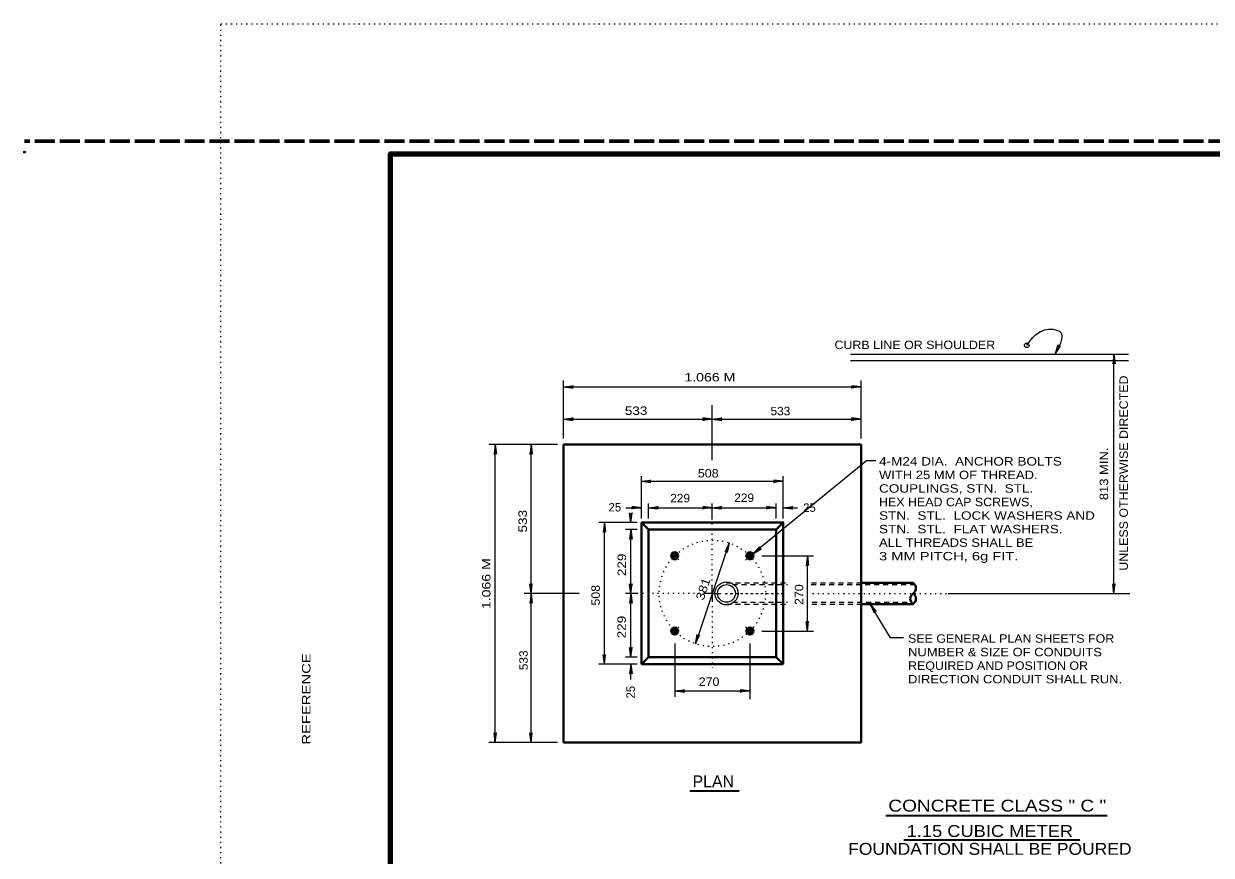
# Model space of a CAD drawing. Extents: x 312583 to 312854, y 144419 to 144597.
# Drawn here: x 312583.5 to 312690.4, y 144521.9 to 144596.8 of the extents above; entities that cross this region are included whole.
import ezdxf
from ezdxf.enums import TextEntityAlignment as Align

# ---------------------------------------------------------------- set-up
doc = ezdxf.new("R2010")
doc.units = 0
doc.header["$LTSCALE"] = 0.3
doc.header["$PDMODE"] = 32
doc.header["$PDSIZE"] = 0.15
for name, pattern in [('DOTTED', [1.5, 0.3, -1.2]), ('LONG_DASHED', [7.5, 6, -1.5]), ('SHORT_DASHED', [2.7, 1.5, -1.2])]:
    doc.linetypes.add(name, pattern=pattern)
for name, color, linetype, lineweight in [('1', 7, 'Continuous', 25), ('2', 7, 'Continuous', 13), ('62', 7, 'DOTTED', 13), ('63', 7, 'LONG_DASHED', 60)]:
    doc.layers.add(name, color=color, linetype=linetype, lineweight=lineweight)

msp = doc.modelspace()

# ---------------------------------------------------------------- linework, layer by layer
at = {"layer": '1', "lineweight": 40}
for p, q in [((312632.0713, 144558.8961), (312658.9047, 144558.8961)), ((312632.0713, 144558.8961), (312632.0713, 144532.0628)), ((312658.9047, 144558.8961), (312658.9047, 144532.0628)), ((312639.094, 144551.8734), (312639.094, 144539.0931)), ((312639.738, 144551.2294), (312639.094, 144551.8734)), ((312651.238, 144551.2294), (312651.8743, 144551.8734)), ((312639.738, 144551.2294), (312639.738, 144539.7294)), ((312639.738, 144551.2294), (312651.238, 144551.2294)), ((312651.238, 144551.2294), (312651.238, 144539.7294)), ((312658.9047, 144546.4378), (312663.5737, 144546.4378)), ((312658.9047, 144544.5211), (312663.5737, 144544.5211)), ((312639.094, 144539.0931), (312639.738, 144539.7294)), ((312639.094, 144539.0931), (312651.8743, 144539.0931)), ((312639.738, 144539.7294), (312651.238, 144539.7294)), ((312651.238, 144539.7294), (312651.8743, 144539.0931)), ((312632.0713, 144532.0628), (312658.9047, 144532.0628))]:
    msp.add_line(p, q, dxfattribs=at)
at = {"layer": '1', "linetype": 'DOTTED', "lineweight": 13}
for p, q in [((312642.475, 144548.4924), (312641.8157, 144549.1518)), ((312648.4857, 144548.4848), (312648.8767, 144548.8681)), ((312646.7607, 144545.4794), (312652.2577, 144545.4794)), ((312654.527, 144545.4794), (312666.7477, 144545.4794)), ((312642.4673, 144542.4664), (312641.8157, 144541.8148)), ((312648.4857, 144542.4818), (312649.1527, 144541.8148))]:
    msp.add_line(p, q, dxfattribs=at)
at = {"layer": '1', "linetype": 'SHORT_DASHED'}
for p, q in [((312646.7607, 144546.4378), (312652.2577, 144546.4378)), ((312647.2973, 144546.2844), (312652.2577, 144546.2844)), ((312654.3967, 144546.2844), (312663.727, 144546.2844)), ((312654.4197, 144546.4378), (312658.9047, 144546.4378)), ((312646.7607, 144544.5211), (312652.2577, 144544.5211)), ((312647.2973, 144544.6821), (312652.2577, 144544.6821)), ((312654.458, 144544.5211), (312658.9047, 144544.5211)), ((312654.481, 144544.6821), (312663.4203, 144544.6821))]:
    msp.add_line(p, q, dxfattribs=at)
at = {"layer": '1', "lineweight": 158}
msp.add_lwpolyline([(312616.5, 144423.1446), (312616.5, 144585.0846), (312849, 144585.0846)], dxfattribs=at)
at = {"layer": '1', "lineweight": 40}
msp.add_lwpolyline([(312639.094, 144551.8734), (312651.8743, 144551.8734), (312651.8743, 144539.0931)], dxfattribs=at)
at = {"layer": '1', "linetype": 'DOTTED', "lineweight": 13}
msp.add_circle((312645.4861, 144545.4826), 4.7917, dxfattribs=at)
at = {"layer": '1', "lineweight": 40}
for centre, radius in [((312642.0981, 144548.8707), 0.3194), ((312642.0981, 144548.8707), 0.2236), ((312642.0978, 144548.8709), 0.1565), ((312642.0979, 144548.8708), 0.1096), ((312648.8741, 144548.8707), 0.3194), ((312648.8741, 144548.8707), 0.2236), ((312648.8741, 144548.8707), 0.1565), ((312648.8741, 144548.8707), 0.1096), ((312642.0981, 144542.0946), 0.3194), ((312642.0981, 144542.0946), 0.2236), ((312642.0981, 144542.0946), 0.1565), ((312642.0981, 144542.0946), 0.1096), ((312648.8741, 144542.0946), 0.3194), ((312648.8741, 144542.0946), 0.2236), ((312648.8741, 144542.0946), 0.1565), ((312648.8741, 144542.0946), 0.1096)]:
    msp.add_circle(centre, radius, dxfattribs=at)
at = {"layer": '1'}
for radius in [1.0382, 0.7986]:
    msp.add_circle((312646.7639, 144545.4826), radius, dxfattribs=at)
at = {"layer": '1', "lineweight": 40}
for centre, start, end in [((312663.242, 144545.9618), 304.79073, 55.20927), ((312663.9079, 144545.0035), 124.79073, 235.20928), ((312663.242, 144545.0035), 304.79073, 55.20927)]:
    msp.add_arc(centre, 0.5835, start, end, dxfattribs=at)
at = {"layer": '1'}
msp.add_point((312583.526, 144585.2246), dxfattribs=at)
at = {"layer": '2'}
for p, q in [((312676.3884, 144567.0304), (312676.6567, 144567.8584)), ((312676.3884, 144567.0304), (312676.8484, 144567.7664)), ((312676.6567, 144567.8584), (312676.6414, 144567.5671)), ((312676.8484, 144567.7664), (312676.6414, 144567.5671)), ((312657.9233, 144567.0304), (312682.98, 144567.0304)), ((312681.6734, 144567.0304), (312681.5661, 144566.1641)), ((312681.6734, 144545.4794), (312681.6734, 144567.0304)), ((312681.6734, 144567.0304), (312681.7808, 144566.1641)), ((312657.9233, 144566.4478), (312682.98, 144566.4478)), ((312681.5661, 144566.1641), (312681.6734, 144566.4401)), ((312681.7808, 144566.1641), (312681.6734, 144566.4401)), ((312632.0713, 144559.4328), (312632.0713, 144564.6614)), ((312632.0713, 144559.4328), (312632.0713, 144564.6614)), ((312658.9047, 144559.4328), (312658.9047, 144564.6614)), ((312658.9047, 144559.4328), (312658.9047, 144564.5924)), ((312632.0713, 144564.0788), (312632.9377, 144564.1861)), ((312632.0713, 144564.0788), (312632.9377, 144564.1861)), ((312632.0713, 144564.0788), (312658.9047, 144564.0788)), ((312632.0713, 144564.0788), (312632.9377, 144563.9714)), ((312632.0713, 144564.0788), (312658.9047, 144564.0788)), ((312632.0713, 144564.0788), (312632.9377, 144563.9714)), ((312632.9377, 144564.1861), (312632.6617, 144564.0788)), ((312632.9377, 144564.1861), (312632.6617, 144564.0788)), ((312632.9377, 144563.9714), (312632.6617, 144564.0788)), ((312632.9377, 144563.9714), (312632.6617, 144564.0788)), ((312658.0383, 144564.1861), (312658.3143, 144564.0788)), ((312658.9047, 144564.0788), (312658.0383, 144564.1861)), ((312658.0383, 144564.1861), (312658.3143, 144564.0788)), ((312658.9047, 144564.0788), (312658.0383, 144564.1861)), ((312658.0383, 144563.9714), (312658.3143, 144564.0788)), ((312658.9047, 144564.0788), (312658.0383, 144563.9714)), ((312658.0383, 144563.9714), (312658.3143, 144564.0788)), ((312658.9047, 144564.0788), (312658.0383, 144563.9714)), ((312645.488, 144557.4778), (312645.488, 144562.4458)), ((312632.0713, 144561.1731), (312632.9377, 144561.2804)), ((312632.0713, 144561.1731), (312632.9377, 144561.2804)), ((312632.9377, 144561.2804), (312632.6617, 144561.1731)), ((312632.9377, 144561.2804), (312632.6617, 144561.1731)), ((312644.6217, 144561.2804), (312644.8977, 144561.1731)), ((312645.488, 144561.1731), (312644.6217, 144561.2804)), ((312644.6217, 144561.2804), (312644.8977, 144561.1731)), ((312645.488, 144561.1731), (312644.6217, 144561.2804)), ((312645.488, 144557.4778), (312645.488, 144561.6944)), ((312645.488, 144561.1731), (312646.3543, 144561.2804)), ((312645.488, 144561.1731), (312646.3543, 144561.2804)), ((312646.3543, 144561.2804), (312646.0783, 144561.1731)), ((312646.3543, 144561.2804), (312646.0783, 144561.1731)), ((312658.0383, 144561.2804), (312658.3143, 144561.1731)), ((312658.9047, 144561.1731), (312658.0383, 144561.2804)), ((312658.0383, 144561.2804), (312658.3143, 144561.1731)), ((312658.9047, 144561.1731), (312658.0383, 144561.2804)), ((312632.0713, 144561.1731), (312632.9377, 144561.0658)), ((312632.0713, 144561.1731), (312632.9377, 144561.0658)), ((312632.9377, 144561.0658), (312632.6617, 144561.1731)), ((312632.9377, 144561.0658), (312632.6617, 144561.1731)), ((312644.6217, 144561.0658), (312644.8977, 144561.1731)), ((312645.488, 144561.1731), (312644.6217, 144561.0658)), ((312644.6217, 144561.0658), (312644.8977, 144561.1731)), ((312645.488, 144561.1731), (312644.6217, 144561.0658)), ((312645.488, 144561.1731), (312646.3543, 144561.0658)), ((312645.488, 144561.1731), (312646.3543, 144561.0658)), ((312646.3543, 144561.0658), (312646.0783, 144561.1731)), ((312646.3543, 144561.0658), (312646.0783, 144561.1731)), ((312658.0383, 144561.0658), (312658.3143, 144561.1731)), ((312658.9047, 144561.1731), (312658.0383, 144561.0658)), ((312658.0383, 144561.0658), (312658.3143, 144561.1731)), ((312658.9047, 144561.1731), (312658.0383, 144561.0658)), ((312631.5347, 144558.8961), (312625.3477, 144558.8961)), ((312631.5347, 144558.8961), (312625.3477, 144558.8961)), ((312625.9303, 144558.8961), (312625.823, 144558.0298)), ((312625.9303, 144558.8961), (312625.823, 144558.0298)), ((312625.823, 144558.0298), (312625.9303, 144558.3058)), ((312625.823, 144558.0298), (312625.9303, 144558.3058)), ((312625.9303, 144532.0628), (312625.9303, 144558.8961)), ((312625.9303, 144558.8961), (312626.0377, 144558.0298)), ((312625.9303, 144532.0628), (312625.9303, 144558.8961)), ((312625.9303, 144558.8961), (312626.0377, 144558.0298)), ((312626.0377, 144558.0298), (312625.9303, 144558.3058)), ((312626.0377, 144558.0298), (312625.9303, 144558.3058)), ((312629.158, 144558.8961), (312629.0507, 144558.0298)), ((312629.158, 144558.8961), (312629.0507, 144558.0298)), ((312629.0507, 144558.0298), (312629.158, 144558.3058)), ((312629.0507, 144558.0298), (312629.158, 144558.3058)), ((312629.158, 144558.8961), (312629.2653, 144558.0298)), ((312629.158, 144558.8961), (312629.2653, 144558.0298)), ((312629.2653, 144558.0298), (312629.158, 144558.3058)), ((312629.2653, 144558.0298), (312629.158, 144558.3058)), ((312659.3647, 144557.4088), (312649.145, 144549.0368)), ((312660.2157, 144557.4088), (312659.3647, 144557.4088)), ((312639.094, 144552.2414), (312639.094, 144556.0518)), ((312651.8743, 144552.2414), (312651.8743, 144556.0518)), ((312639.094, 144555.5764), (312639.9603, 144555.6838)), ((312639.094, 144555.5764), (312651.8743, 144555.5764)), ((312639.094, 144555.5764), (312639.9603, 144555.4691)), ((312639.9603, 144555.6838), (312639.6843, 144555.5764)), ((312639.9603, 144555.4691), (312639.6843, 144555.5764)), ((312651.008, 144555.6838), (312651.284, 144555.5764)), ((312651.8743, 144555.5764), (312651.008, 144555.6838)), ((312651.008, 144555.4691), (312651.284, 144555.5764)), ((312651.8743, 144555.5764), (312651.008, 144555.4691)), ((312637.691, 144553.1921), (312639.094, 144553.1921)), ((312638.036, 144552.7398), (312638.1433, 144552.4638)), ((312638.1433, 144551.8734), (312638.036, 144552.7398)), ((312638.2507, 144552.7398), (312638.1433, 144552.4638)), ((312638.1433, 144551.8734), (312638.2507, 144552.7398)), ((312638.2277, 144553.2994), (312638.5037, 144553.1921)), ((312639.094, 144553.1921), (312638.2277, 144553.2994)), ((312638.2277, 144553.0848), (312638.5037, 144553.1921)), ((312639.094, 144553.1921), (312638.2277, 144553.0848)), ((312639.738, 144552.2414), (312639.738, 144553.5678)), ((312639.738, 144553.1921), (312640.6043, 144553.2994)), ((312639.738, 144553.1921), (312645.488, 144553.1921)), ((312639.738, 144553.1921), (312640.6043, 144553.0848)), ((312640.6043, 144553.2994), (312640.3283, 144553.1921)), ((312640.6043, 144553.0848), (312640.3283, 144553.1921)), ((312644.6217, 144553.2994), (312644.8977, 144553.1921)), ((312645.488, 144553.1921), (312644.6217, 144553.2994)), ((312644.6217, 144553.0848), (312644.8977, 144553.1921)), ((312645.488, 144553.1921), (312644.6217, 144553.0848)), ((312645.488, 144552.2108), (312645.488, 144553.5678)), ((312645.488, 144553.1921), (312646.3543, 144553.2994)), ((312645.488, 144553.1921), (312651.238, 144553.1921)), ((312645.488, 144553.1921), (312646.3543, 144553.0848)), ((312646.3543, 144553.2994), (312646.0783, 144553.1921)), ((312646.3543, 144553.0848), (312646.0783, 144553.1921)), ((312650.3717, 144553.2994), (312650.6477, 144553.1921)), ((312651.238, 144553.1921), (312650.3717, 144553.2994)), ((312650.3717, 144553.0848), (312650.6477, 144553.1921)), ((312651.238, 144553.1921), (312650.3717, 144553.0848)), ((312651.238, 144552.2414), (312651.238, 144553.5678)), ((312651.8743, 144553.1921), (312652.7407, 144553.2994)), ((312651.8743, 144553.1921), (312653.17, 144553.1921)), ((312651.8743, 144553.1921), (312652.7407, 144553.0848)), ((312652.7407, 144553.2994), (312652.4647, 144553.1921)), ((312652.7407, 144553.0848), (312652.4647, 144553.1921)), ((312638.726, 144551.8734), (312635.2607, 144551.8734)), ((312635.7667, 144551.8734), (312635.6593, 144551.0071)), ((312635.7667, 144539.0931), (312635.7667, 144551.8734)), ((312635.7667, 144551.8734), (312635.874, 144551.0071)), ((312638.1433, 144551.8734), (312638.1433, 144552.6631)), ((312635.6593, 144551.0071), (312635.7667, 144551.2831)), ((312635.874, 144551.0071), (312635.7667, 144551.2831)), ((312638.726, 144551.2294), (312637.668, 144551.2294)), ((312638.1433, 144551.2294), (312638.036, 144550.3631)), ((312638.036, 144550.3631), (312638.1433, 144550.6391)), ((312638.1433, 144551.2294), (312638.2507, 144550.3631)), ((312638.2507, 144550.3631), (312638.1433, 144550.6391)), ((312647.0137, 144550.0258), (312643.9623, 144540.9408)), ((312647.0137, 144550.0258), (312646.638, 144549.2361)), ((312647.0137, 144550.0258), (312646.8373, 144549.1671)), ((312649.145, 144549.0368), (312649.7507, 144549.6654)), ((312649.145, 144549.0368), (312649.8887, 144549.5044)), ((312649.7507, 144549.6654), (312649.605, 144549.4124)), ((312649.8887, 144549.5044), (312649.605, 144549.4124)), ((312646.638, 144549.2361), (312646.822, 144549.4661)), ((312646.8373, 144549.1671), (312646.822, 144549.4661)), ((312649.9347, 144548.8681), (312654.5883, 144548.8681)), ((312654.0593, 144548.8681), (312653.952, 144548.0018)), ((312654.0593, 144542.0908), (312654.0593, 144548.8681)), ((312654.0593, 144548.8681), (312654.1667, 144548.0018)), ((312653.952, 144548.0018), (312654.0593, 144548.2778)), ((312654.1667, 144548.0018), (312654.0593, 144548.2778)), ((312629.0507, 144546.3458), (312629.158, 144546.0698)), ((312629.158, 144545.4794), (312629.0507, 144546.3458)), ((312629.0507, 144546.3458), (312629.158, 144546.0698)), ((312629.158, 144545.4794), (312629.0507, 144546.3458)), ((312629.2653, 144546.3458), (312629.158, 144546.0698)), ((312629.158, 144545.4794), (312629.2653, 144546.3458)), ((312629.2653, 144546.3458), (312629.158, 144546.0698)), ((312629.158, 144545.4794), (312629.2653, 144546.3458)), ((312638.036, 144546.3458), (312638.1433, 144546.0698)), ((312638.1433, 144545.4794), (312638.036, 144546.3458)), ((312638.2507, 144546.3458), (312638.1433, 144546.0698)), ((312638.1433, 144545.4794), (312638.2507, 144546.3458)), ((312681.5661, 144546.3458), (312681.6734, 144546.0698)), ((312681.6734, 144545.4794), (312681.5661, 144546.3458)), ((312681.7808, 144546.3458), (312681.6734, 144546.0698)), ((312681.6734, 144545.4794), (312681.7808, 144546.3458)), ((312633.4897, 144545.4794), (312628.5217, 144545.4794)), ((312633.4897, 144545.4794), (312628.5217, 144545.4794)), ((312629.158, 144545.4794), (312629.0507, 144544.6131)), ((312629.158, 144545.4794), (312629.0507, 144544.6131)), ((312629.158, 144545.4794), (312629.2653, 144544.6131)), ((312629.158, 144532.0628), (312629.158, 144545.4794)), ((312629.158, 144545.4794), (312629.2653, 144544.6131)), ((312638.7797, 144545.4794), (312637.668, 144545.4794)), ((312638.1433, 144545.4794), (312638.036, 144544.6131)), ((312638.1433, 144545.4794), (312638.2507, 144544.6131)), ((312645.488, 144545.4794), (312644.7213, 144545.4794)), ((312645.488, 144545.4794), (312645.488, 144546.2461)), ((312645.488, 144545.4794), (312646.2547, 144545.4794)), ((312645.488, 144545.4794), (312645.488, 144544.7128)), ((312666.7477, 144545.4794), (312683.0921, 144545.4794)), ((312629.0507, 144544.6131), (312629.158, 144544.8891)), ((312629.0507, 144544.6131), (312629.158, 144544.8891)), ((312629.2653, 144544.6131), (312629.158, 144544.8891)), ((312629.2653, 144544.6131), (312629.158, 144544.8891)), ((312638.036, 144544.6131), (312638.1433, 144544.8891)), ((312638.2507, 144544.6131), (312638.1433, 144544.8891)), ((312659.7097, 144544.5211), (312660.0623, 144543.7238)), ((312659.7097, 144544.5211), (312660.2463, 144543.8388)), ((312660.0623, 144543.7238), (312660.0087, 144544.0151)), ((312660.2463, 144543.8388), (312660.0087, 144544.0151)), ((312649.9347, 144542.0908), (312654.5883, 144542.0908)), ((312653.952, 144542.9571), (312654.0593, 144542.6811)), ((312654.0593, 144542.0908), (312653.952, 144542.9571)), ((312654.1667, 144542.9571), (312654.0593, 144542.6811)), ((312654.0593, 144542.0908), (312654.1667, 144542.9571)), ((312642.0993, 144540.9791), (312642.0993, 144536.1721)), ((312643.9623, 144540.9408), (312644.131, 144541.7918)), ((312643.9623, 144540.9408), (312644.338, 144541.7304)), ((312644.131, 144541.7918), (312644.1463, 144541.5004)), ((312644.338, 144541.7304), (312644.1463, 144541.5004)), ((312648.8767, 144540.9791), (312648.8767, 144535.9421)), ((312635.6593, 144539.9594), (312635.7667, 144539.6834)), ((312635.7667, 144539.0931), (312635.6593, 144539.9594)), ((312635.874, 144539.9594), (312635.7667, 144539.6834)), ((312635.7667, 144539.0931), (312635.874, 144539.9594)), ((312638.036, 144540.5958), (312638.1433, 144540.3198)), ((312638.1433, 144539.7294), (312638.036, 144540.5958)), ((312638.2507, 144540.5958), (312638.1433, 144540.3198)), ((312638.1433, 144539.7294), (312638.2507, 144540.5958)), ((312638.726, 144539.0931), (312635.2607, 144539.0931)), ((312638.726, 144539.7294), (312637.668, 144539.7294)), ((312638.1433, 144539.0931), (312638.036, 144538.2268)), ((312638.1433, 144537.7208), (312638.1433, 144539.0931)), ((312638.1433, 144539.0931), (312638.2507, 144538.2268)), ((312638.036, 144538.2268), (312638.1433, 144538.5028)), ((312638.2507, 144538.2268), (312638.1433, 144538.5028)), ((312642.0993, 144536.6934), (312642.9657, 144536.8008)), ((312642.0993, 144536.6934), (312648.8767, 144536.6934)), ((312642.0993, 144536.6934), (312642.9657, 144536.5861)), ((312642.9657, 144536.8008), (312642.6897, 144536.6934)), ((312642.9657, 144536.5861), (312642.6897, 144536.6934)), ((312648.0103, 144536.8008), (312648.2863, 144536.6934)), ((312648.8767, 144536.6934), (312648.0103, 144536.8008)), ((312648.0103, 144536.5861), (312648.2863, 144536.6934)), ((312648.8767, 144536.6934), (312648.0103, 144536.5861)), ((312625.823, 144532.9291), (312625.9303, 144532.6531)), ((312625.9303, 144532.0628), (312625.823, 144532.9291)), ((312625.823, 144532.9291), (312625.9303, 144532.6531)), ((312625.9303, 144532.0628), (312625.823, 144532.9291)), ((312626.0377, 144532.9291), (312625.9303, 144532.6531)), ((312625.9303, 144532.0628), (312626.0377, 144532.9291)), ((312626.0377, 144532.9291), (312625.9303, 144532.6531)), ((312625.9303, 144532.0628), (312626.0377, 144532.9291)), ((312629.0507, 144532.9291), (312629.158, 144532.6531)), ((312629.158, 144532.0628), (312629.0507, 144532.9291)), ((312629.0507, 144532.9291), (312629.158, 144532.6531)), ((312629.158, 144532.0628), (312629.0507, 144532.9291)), ((312629.2653, 144532.9291), (312629.158, 144532.6531)), ((312629.158, 144532.0628), (312629.2653, 144532.9291)), ((312629.2653, 144532.9291), (312629.158, 144532.6531)), ((312629.158, 144532.0628), (312629.2653, 144532.9291)), ((312631.5347, 144532.0628), (312625.3477, 144532.0628)), ((312631.5347, 144532.0628), (312625.3477, 144532.0628))]:
    msp.add_line(p, q, dxfattribs=at)
at = {"layer": '2', "linetype": 'DOTTED'}
for p, q in [((312645.488, 144546.6294), (312645.488, 144552.2108)), ((312644.338, 144545.4794), (312638.7797, 144545.4794)), ((312646.638, 144545.4794), (312652.135, 144545.4794)), ((312645.488, 144544.3294), (312645.488, 144538.7788))]:
    msp.add_line(p, q, dxfattribs=at)
at = {"layer": '2', "lineweight": 35}
for p, q in [((312643.459, 144527.7068), (312647.9131, 144527.7068)), ((312661.1113, 144525.4666), (312681.0557, 144525.4666)), ((312662.7517, 144523.2829), (312678.5924, 144523.2829))]:
    msp.add_line(p, q, dxfattribs=at)
at = {"layer": '2'}
for points in [[(312632.0713, 144561.1731), (312645.488, 144561.1731), (312658.9047, 144561.1731)], [(312632.0713, 144561.1731), (312645.488, 144561.1731), (312658.9047, 144561.1731)], [(312629.158, 144532.0628), (312629.158, 144545.4794), (312629.158, 144558.8961)], [(312638.1433, 144539.7294), (312638.1433, 144545.4794), (312638.1433, 144551.2294)], [(312662.7227, 144541.4698), (312661.542, 144541.4698), (312659.7097, 144544.5211)]]:
    msp.add_lwpolyline(points, dxfattribs=at)
at = {"layer": '2', "lineweight": 25}
msp.add_circle((312673.8188, 144567.8207), 0.2081, dxfattribs=at)
at = {"layer": '2'}
msp.add_spline([(312673.82, 144567.8201), (312674.74, 144568.8704), (312676.189, 144569.2691), (312676.9174, 144568.9394), (312676.8484, 144568.0194), (312676.3884, 144567.0304)], degree=3, dxfattribs=at)
at = {"layer": '62'}
for p, q in [((312601.2, 144596.7846), (312853.5, 144596.7846)), ((312601.2, 144418.5846), (312601.2, 144596.7846))]:
    msp.add_line(p, q, dxfattribs=at)
at = {"layer": '63'}
msp.add_line((312851.75, 144586.2246), (312583.526, 144586.2246), dxfattribs=at)

# ---------------------------------------------------------------- texts
at = {"layer": '1', "width": 1.3}
msp.add_text('REFERENCE                                                              ', height=0.7682, rotation=90, dxfattribs=at).set_placement((312609.2854, 144531.8549))
at = {"layer": '2'}
for s, width, p in [('CURB LINE OR SHOULDER', 1.1, (312656.4939, 144567.4852)), ('1.066 M', 1.25, (312642.9733, 144564.5696)), ('533 ', 1.2, (312637.6052, 144561.5561)), ('533', 1.05, (312650.7328, 144561.5201)), ('4-M24 DIA.  ANCHOR BOLTS', 1.2, (312660.507, 144556.9938)), ('508', 1.1, (312644.1872, 144555.9235)), ('WITH 25 MM OF THREAD.', 1.15, (312660.507, 144555.7738)), ('COUPLINGS, STN.  STL.', 1.2, (312660.507, 144554.5538)), ('229', 1.05, (312641.7, 144553.683)), ('229', 1.05, (312647.4651, 144553.7184)), ('HEX HEAD CAP SCREWS,', 1.1, (312660.507, 144553.3338)), ('STN.  STL.  LOCK WASHERS AND', 1.2, (312660.507, 144552.1138)), ('STN.  STL.  FLAT WASHERS.', 1.2, (312660.507, 144550.8938)), ('ALL THREADS SHALL BE', 1.15, (312660.507, 144549.6738)), ('3 MM PITCH, 6g FIT.', 1.3, (312660.507, 144548.4538)), ('SEE GENERAL PLAN SHEETS FOR', 1.1, (312663.1213, 144541.0365)), ('NUMBER & SIZE OF CONDUITS', 1.15, (312663.1213, 144539.8165)), ('REQUIRED AND POSITION OR', 1.1, (312663.1213, 144538.5965)), ('270', 1.1, (312644.2613, 144537.1483)), ('DIRECTION CONDUIT SHALL RUN.', 1.15, (312663.1213, 144537.3765))]:
    msp.add_text(s, height=0.76, dxfattribs=dict(at, width=width)).set_placement(p)
for s, rotation, width, p in [('UNLESS OTHERWISE DIRECTED', 90, 1.1, (312682.9236, 144547.5248)), ('813 MIN.', 90, 1.15, (312681.1473, 144553.8759)), ('533 ', 90, 1.2, (312628.7812, 144550.9633)), ('1.066 M', 90, 1.25, (312625.4999, 144544.0618)), ('229 ', 90, 1.2, (312637.7104, 144547.0347)), ('381 ', 71.435, 1.2, (312644.6916, 144544.7938)), ('508', 90, 1.1, (312635.352, 144544.3817)), ('270', 90, 1.1, (312653.6797, 144544.4381)), ('229 ', 90, 1.2, (312637.6923, 144541.4304)), ('533', 90, 1.05, (312628.8543, 144538.5637))]:
    msp.add_text(s, height=0.76, rotation=rotation, dxfattribs=dict(at, width=width)).set_placement(p)
for p in [(312636.1412, 144552.8615), (312653.676, 144552.8251)]:
    msp.add_text('25', height=0.76, dxfattribs=at).set_placement(p)
msp.add_text('25', height=0.76, rotation=90, dxfattribs=at).set_placement((312638.5029, 144536.016))
msp.add_text('PLAN', height=1.07, dxfattribs=at).set_placement((312645.5747, 144528.0154), align=Align.CENTER)
for s, width, p in [('CONCRETE CLASS " C "', 1.2, (312671.1622, 144525.8341)), ('1.15 CUBIC METER', 1.15, (312670.4929, 144523.5437)), ('FOUNDATION SHALL BE POURED', 1.1, (312670.493, 144521.9371))]:
    msp.add_text(s, height=1.07, dxfattribs=dict(at, width=width)).set_placement(p, align=Align.CENTER)

doc.saveas('drawing.dxf')
